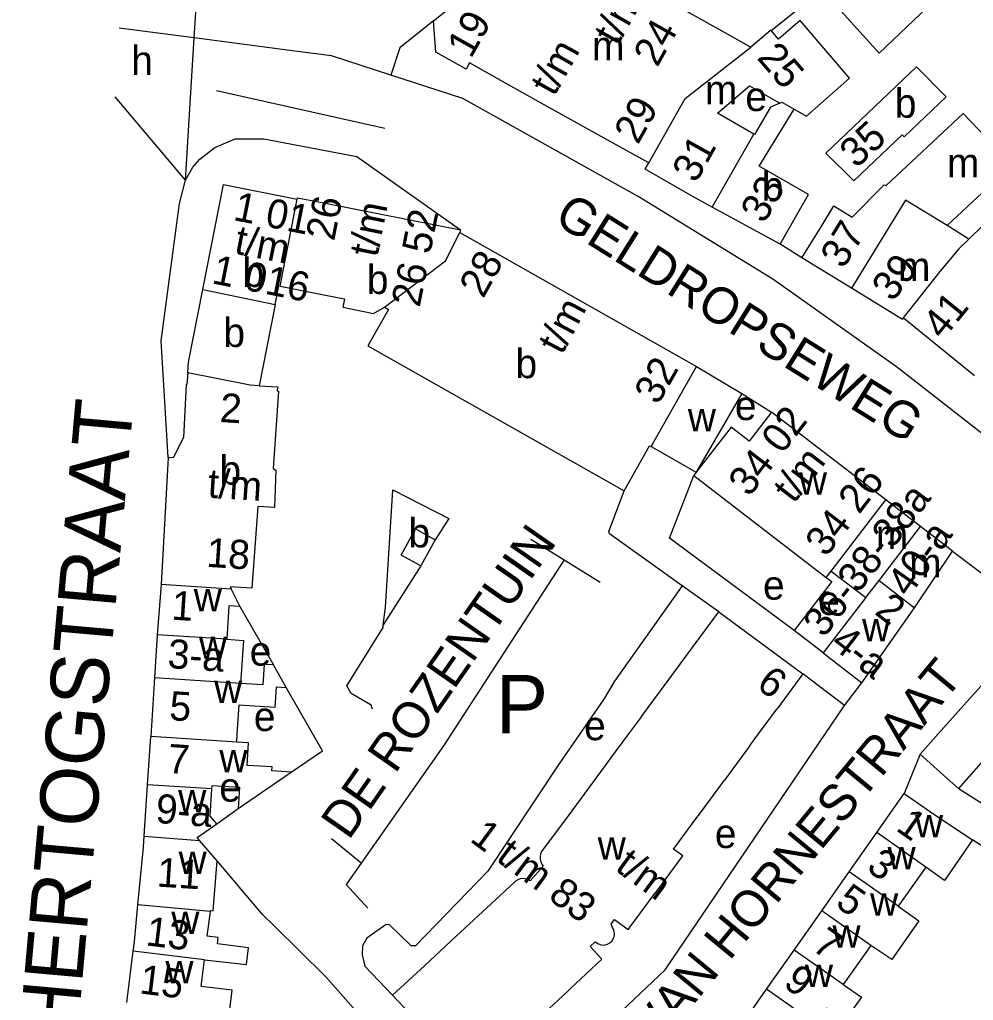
# Model space of a CAD drawing. Extents: x 161141 to 163125, y 381621 to 383200.
# Drawn here: x 161858 to 161989.1, y 382713.4 to 382848.2 of the extents above; entities that cross this region are included whole.
import ezdxf

# ---------------------------------------------------------------- set-up
doc = ezdxf.new("R2010")
doc.units = 0
for name, color, linetype in [('BLT_Basislijn', 7, 'Continuous'), ('BLT_Bebouwing', 7, 'Continuous'), ('BLT_Centroide', 7, 'Continuous'), ('BLT_Huisnummer', 7, 'Continuous'), ('BLT_Huisnummer_ tussenligend', 7, 'Continuous'), ('BLT_Huisnummer_reeks', 7, 'Continuous'), ('BLT_Onderverdeling_panden', 7, 'Continuous'), ('BLT_Straatnaam', 7, 'Continuous'), ('BLT_Straatnaam_hoofdweg', 7, 'Continuous'), ('BLT_Tekst_parkeren', 7, 'Continuous'), ('BLT_Vlakafsluiter', 7, 'Continuous')]:
    doc.layers.add(name, color=color, linetype=linetype)

msp = doc.modelspace()

# ---------------------------------------------------------------- linework, layer by layer
at = {"layer": 'BLT_Basislijn'}
for p, q in [((161961.29, 382846.71), (161968.27, 382852.33)), ((161895.8, 382843.88), (161881.98, 382845.71)), ((161885.05, 382838.45), (161908.16, 382833.27)), ((161965.52, 382815.44), (161962.51, 382817.34)), ((161957.24, 382796.8), (161961.34, 382794.24)), ((161928.24, 382776.76), (161932.83, 382773.93)), ((161913.14, 382773.1), (161907.95, 382764.98)), ((161932.83, 382773.93), (161916.24, 382748.35)), ((161932.83, 382773.93), (161937.79, 382770.88)), ((161954.08, 382766.77), (161949.04, 382770.37)), ((161888.23, 382767.53), (161892.87, 382759.47)), ((161968.43, 382761.13), (161964.43, 382764.21)), ((161971.38, 382753.92), (161965.62, 382758.24)), ((161971.38, 382753.92), (161973.75, 382757.02)), ((161916.24, 382748.35), (161904.92, 382732.23)), ((161981.75, 382747.2), (161979.57, 382741.82)), ((161885.1, 382737.63), (161888.01, 382739.72)), ((161904.92, 382732.23), (161900.83, 382735.55)), ((161996.85, 382730.23), (161988.94, 382735.42)), ((161904.92, 382732.23), (161902.84, 382729.28)), ((161902.84, 382729.28), (161905.85, 382726.02))]:
    msp.add_line(p, q, dxfattribs=at)
for points in [[(162000.63, 382866.97), (161976.12, 382843.61), (161968.27, 382852.33)], [(161914.87, 382848.05), (161910.22, 382844.31), (161909.01, 382840.57)], [(162009.83, 382774.47), (162008.37, 382775.78), (161991.84, 382790.04), (161978.52, 382800.47), (161961.51, 382812.5), (161943, 382823.9), (161918.9, 382837.38), (161909.01, 382840.57)], [(161880.79, 382826.11), (161881.79, 382827.9), (161882.74, 382829.01), (161884.8, 382830.62), (161887.61, 382831.82), (161891.56, 382831.81), (161904.33, 382829.38), (161918.58, 382819.28)], [(161878.4, 382787.98), (161877.45, 382804.06), (161879.93, 382822.9), (161880.79, 382826.11)], [(161964.43, 382764.21), (161947.31, 382776.9), (161950.65, 382785.52)], [(161907.95, 382764.98), (161908.25, 382767.39), (161909.27, 382783.54), (161916.97, 382779.59), (161915.1, 382776.69)], [(161949.04, 382770.37), (161939.06, 382777.49), (161938.96, 382777.81), (161941.06, 382783.4)], [(161949.04, 382770.37), (161939.76, 382757.24), (161938.26, 382754.75), (161932.01, 382745.7), (161922.34, 382731.11), (161912.4, 382720.87), (161911.82, 382720.87), (161908.83, 382723.74), (161908.35, 382723.79), (161905.71, 382721.89), (161905.09, 382720.85), (161905.06, 382719.61), (161905.41, 382718.04), (161909.25, 382714.07)], [(161968.86, 382771.51), (161969.61, 382770.94), (161964.43, 382764.21)], [(161906.5, 382753.39), (161906.28, 382753.96), (161903.53, 382755.56), (161902.94, 382756.61), (161907.93, 382764.64), (161907.95, 382764.98)], [(161895.29, 382744.75), (161899.61, 382747.67), (161894.62, 382756.38)], [(161921.05, 382693.28), (161946.73, 382717.54), (161971.38, 382753.92)], [(161892.98, 382723.59), (161891.37, 382725.18), (161885.15, 382732.53)], [(161892.98, 382723.59), (161900, 382716.62), (161907.64, 382708.03)]]:
    msp.add_lwpolyline(points, dxfattribs=at)
at = {"layer": 'BLT_Bebouwing'}
for p, q in [((161914.87, 382848.05), (161921.65, 382853.48)), ((161915.17, 382843.73), (161914.87, 382848.05)), ((161955.63, 382846.03), (161958.47, 382844.43)), ((161924.76, 382839.48), (161919.83, 382842.24)), ((161929.69, 382836.73), (161924.76, 382839.48)), ((161934.62, 382833.98), (161929.69, 382836.73)), ((161939.55, 382831.22), (161934.62, 382833.98)), ((161944.45, 382828.5), (161939.55, 382831.22)), ((161885.99, 382825.52), (161886.01, 382825.52)), ((161886.01, 382825.52), (161896.14, 382823.52)), ((161962.51, 382817.34), (161953.17, 382822.43)), ((161918.58, 382819.28), (161918.51, 382818.93)), ((161918.51, 382818.93), (161951.04, 382800.5)), ((161988.46, 382818.04), (161985.48, 382819.89)), ((161972.33, 382811.27), (161965.52, 382815.44)), ((161893.11, 382809.05), (161890.89, 382797.86)), ((161989.22, 382799.25), (161979.45, 382807.18)), ((161951.04, 382800.5), (161957.24, 382796.8)), ((161957.24, 382796.8), (161950.99, 382785.97)), ((161977.05, 382782.16), (161961.34, 382794.24)), ((161944.77, 382789.52), (161950.99, 382785.97)), ((161878.4, 382787.98), (161877.41, 382770.53)), ((161950.65, 382785.52), (161968.86, 382771.51)), ((161981.8, 382778.51), (161977.05, 382782.16)), ((161986.22, 382775.11), (161981.8, 382778.51)), ((161915.1, 382776.69), (161913.14, 382773.1)), ((161981, 382767.35), (161986.22, 382775.11)), ((161968.86, 382771.51), (161969.53, 382772.38)), ((161969.53, 382772.38), (161974.28, 382768.73)), ((161877.41, 382770.53), (161876.9, 382763.62)), ((161887.05, 382769.91), (161888.23, 382767.53)), ((161974.28, 382768.73), (161968.43, 382761.13)), ((161950.55, 382761.99), (161954.08, 382766.77)), ((161954.08, 382766.77), (161965.62, 382758.24)), ((161973.75, 382757.02), (161981, 382767.35)), ((161876.9, 382763.62), (161876.51, 382757.72)), ((161946.98, 382757.16), (161950.55, 382761.99)), ((161876.51, 382757.72), (161876, 382749.63)), ((161943.45, 382752.39), (161946.98, 382757.16)), ((161875.57, 382743), (161876, 382749.63)), ((161939.85, 382747.52), (161936.31, 382742.73)), ((161875.11, 382735.95), (161875.57, 382743)), ((161936.31, 382742.73), (161932.72, 382737.87)), ((161975.8, 382736.44), (161979.57, 382741.82)), ((161932.72, 382737.87), (161929.95, 382734.13)), ((161882.7, 382735.36), (161882.38, 382735.74)), ((161885.15, 382732.53), (161882.7, 382735.36)), ((161972.01, 382731.05), (161975.8, 382736.44)), ((161929.96, 382731.82), (161928.15, 382729.78)), ((161982.55, 382731.69), (161978.76, 382726.3)), ((161968.23, 382725.66), (161972.01, 382731.05)), ((161926.01, 382729.6), (161922.86, 382726.68)), ((161922.86, 382726.68), (161917.99, 382722.17)), ((161964.44, 382720.27), (161968.23, 382725.66)), ((161917.99, 382722.17), (161913.62, 382718.11)), ((161974.97, 382720.91), (161971.18, 382715.53)), ((161872.72, 382713.05), (161873.59, 382720.12)), ((161960.66, 382714.88), (161964.44, 382720.27)), ((161913.62, 382718.11), (161909.25, 382714.07)), ((161909.25, 382714.07), (161911.55, 382711.58)), ((161956.87, 382709.48), (161960.66, 382714.88))]:
    msp.add_line(p, q, dxfattribs=at)
for points in [[(161938.14, 382855.85), (161955.63, 382846.03)], [(161964.46, 382835.88), (161966.13, 382834.92), (161972.05, 382840.15), (161965.28, 382848.08), (161962.31, 382845.52), (161961.29, 382846.71)], [(161961.29, 382846.71), (161961.24, 382846.77), (161958.47, 382844.43)], [(161919.83, 382842.24), (161919.34, 382841.39), (161915.17, 382843.73)], [(161958.92, 382832.47), (161953.92, 382835.36), (161958.29, 382839.12), (161962.49, 382836.72)], [(161988.46, 382818.04), (162000.01, 382829.28), (162008.96, 382838), (162018.9, 382827.79)], [(161962.49, 382836.72), (161961.21, 382836.16), (161959, 382832.42), (161958.92, 382832.47)], [(161962.51, 382817.34), (161965.01, 382821.68), (161966.43, 382824.14), (161959.65, 382828.06), (161964.46, 382835.88)], [(161965.52, 382815.44), (161968.14, 382819.7), (161969.92, 382822.6), (161972.43, 382821.05), (161976.82, 382825.48), (161977.11, 382825.39), (161987.67, 382835.28), (161994.1, 382828.62)], [(161953.17, 382822.43), (161950.43, 382823.94), (161943.96, 382827.66), (161944.45, 382828.5)], [(161994.1, 382828.62), (161994.43, 382828.26), (161985.48, 382819.89)], [(161883.15, 382811.11), (161885.39, 382822.51), (161885.99, 382825.52)], [(161896.14, 382823.52), (161896.18, 382823.72), (161900, 382822.97), (161918.58, 382819.28)], [(161881.08, 382799.63), (161881.17, 382801.09), (161883.15, 382811.11)], [(161893.11, 382809.05), (161893.62, 382811.6), (161893.78, 382811.57)], [(161893.78, 382811.57), (161900, 382810.34), (161902.63, 382809.82), (161902.4, 382808.65), (161906.64, 382807.81), (161908.13, 382808.69)], [(161979.45, 382807.18), (161979.33, 382806.98), (161972.33, 382811.27)], [(161908.13, 382808.69), (161908.7, 382808.36), (161905.86, 382803.35), (161941.06, 382783.4)], [(161881.08, 382799.63), (161880.98, 382798.03), (161880.87, 382798.04), (161880.5, 382790.74), (161879.08, 382787.96), (161878.4, 382787.98)], [(161890.89, 382797.86), (161893.43, 382797.71), (161893.4, 382797.15), (161893.55, 382797.14), (161892.85, 382786.5), (161893.21, 382786.26), (161893.01, 382781.11), (161890.7, 382781.26), (161889.91, 382770.03)], [(161961.34, 382794.24), (161958.26, 382790.25), (161955.77, 382792.17), (161950.99, 382785.97)], [(161941.06, 382783.4), (161944.58, 382789.62), (161944.77, 382789.52)], [(161950.99, 382785.97), (161950.65, 382785.52)], [(161913.14, 382773.1), (161910.42, 382774.59), (161912.39, 382778.17), (161915.1, 382776.69)], [(161889.91, 382770.03), (161886.9, 382770.23), (161887.05, 382769.91)], [(161888.23, 382767.53), (161886.75, 382767.62), (161886.45, 382763)], [(161886.45, 382763), (161888.73, 382762.85)], [(161888.73, 382762.85), (161888.34, 382756.94)], [(161968.43, 382761.13), (161969.68, 382760.17), (161973.75, 382757.02)], [(161981.75, 382747.2), (161984.26, 382750), (161994.45, 382761.42)], [(161892.87, 382759.47), (161891.59, 382759.55), (161891.41, 382756.74), (161888.34, 382756.94)], [(161894.62, 382756.38), (161892.87, 382759.47)], [(161965.62, 382758.24), (161962.09, 382753.46)], [(161887.82, 382748.86), (161887.89, 382750), (161888.16, 382754.01), (161893.1, 382753.68), (161893.28, 382756.46), (161894.62, 382756.38)], [(161958.54, 382748.61), (161959.56, 382750), (161961.79, 382753.01), (161962.09, 382753.46)], [(161943.45, 382752.39), (161941.68, 382750), (161939.85, 382747.52)], [(161895.29, 382744.75), (161892.66, 382744.91), (161892.7, 382745.46), (161889.25, 382745.67), (161889.43, 382748.75), (161887.82, 382748.86)], [(161955.04, 382743.82), (161958.23, 382748.14), (161958.54, 382748.61)], [(161987.02, 382742.5), (161985.48, 382743.87), (161981.75, 382747.2)], [(161888.01, 382739.72), (161895.29, 382744.75)], [(161951.43, 382738.95), (161954.66, 382743.31), (161955.04, 382743.82)], [(161885.1, 382737.63), (161884.17, 382738.68), (161884.41, 382742.43)], [(161884.41, 382742.43), (161884.43, 382742.89)], [(161884.43, 382742.89), (161888.19, 382742.66), (161888.01, 382739.72)], [(161997.28, 382742.34), (161993.65, 382738.27), (161987.14, 382742.39), (161987.02, 382742.5)], [(161979.57, 382741.82), (161983.66, 382738.95), (161988.94, 382735.42)], [(161947.88, 382734.17), (161951.08, 382738.49), (161951.43, 382738.95)], [(161882.38, 382735.74), (161885.1, 382737.63)], [(161874.23, 382726.5), (161875.01, 382734.4), (161875.11, 382735.95)], [(161988.94, 382735.42), (161985.11, 382729.84), (161982.55, 382731.69)], [(161929.95, 382734.13), (161929.73, 382733.83), (161929.58, 382733.49), (161929.51, 382733.14), (161929.51, 382732.77), (161929.6, 382732.41), (161929.76, 382732.08), (161929.96, 382731.82)], [(161949.15, 382733.23), (161947.88, 382734.17)], [(161945.56, 382728.37), (161949.15, 382733.23)], [(161884.23, 382725.71), (161884.6, 382725.66), (161885.15, 382732.53)], [(161928.15, 382729.78), (161927.84, 382729.96), (161927.49, 382730.07), (161927.14, 382730.1), (161926.78, 382730.05), (161926.45, 382729.93), (161926.15, 382729.73), (161926.01, 382729.6)], [(161941.63, 382723.09), (161945.17, 382727.87), (161945.56, 382728.37)], [(161873.59, 382720.12), (161873.76, 382721.46), (161874.23, 382726.5)], [(161978.76, 382726.3), (161981.6, 382724.3), (161977.85, 382718.97), (161974.97, 382720.91)], [(161883.37, 382718.92), (161887.53, 382718.47), (161889.15, 382718.29), (161889.45, 382720.58), (161885.18, 382721.14), (161885.29, 382721.98), (161883.76, 382722.19), (161884.21, 382725.56)], [(161884.21, 382725.56), (161884.23, 382725.71)], [(161937.44, 382721.16), (161937.77, 382721.03), (161938.12, 382720.97), (161938.47, 382720.99), (161938.8, 382721.1), (161939.11, 382721.27), (161939.37, 382721.51), (161939.56, 382721.8), (161939.69, 382722.13), (161939.74, 382722.48), (161939.71, 382722.83), (161939.6, 382723.16), (161939.49, 382723.37)], [(161939.49, 382723.37), (161939.28, 382723.82), (161939.76, 382724.47)], [(161939.76, 382724.47), (161941.63, 382723.09)], [(161936.39, 382720.78), (161937.07, 382721.41), (161937.44, 382721.16)], [(161938.01, 382719.03), (161936.39, 382720.78)], [(161883.19, 382717.45), (161883.37, 382718.92)], [(161933.68, 382715.01), (161938.01, 382719.03)], [(161886.79, 382711.32), (161887.21, 382714.74), (161882.92, 382715.26), (161883.19, 382717.45)], [(161971.18, 382715.53), (161973.69, 382713.82), (161971.37, 382710.53), (161968.89, 382712.27), (161967.39, 382710.14)], [(161928.84, 382710.46), (161933.28, 382714.57), (161933.68, 382715.01)]]:
    msp.add_lwpolyline(points, dxfattribs=at)
msp.add_lwpolyline([(161981.28, 382841.69), (161968.8, 382829.84), (161972.65, 382826.03), (161979.28, 382832.35), (161979.55, 382832.07), (161985.35, 382837.6)], close=True, dxfattribs=at)
at = {"layer": 'BLT_Onderverdeling_panden'}
for p, q in [((161949.46, 382837.35), (161958.47, 382844.43)), ((161944.45, 382828.5), (161949.46, 382837.35)), ((161953.17, 382822.43), (161958.92, 382832.47)), ((161893.78, 382811.57), (161896.14, 382823.52)), ((161883.15, 382811.11), (161893.11, 382809.05)), ((161944.77, 382789.52), (161951.04, 382800.5)), ((161969.53, 382772.38), (161977.05, 382782.16)), ((161976.11, 382771.11), (161981.8, 382778.51)), ((161887.05, 382769.91), (161877.41, 382770.53)), ((161974.28, 382768.73), (161976.11, 382771.11)), ((161976.11, 382771.11), (161981, 382767.35)), ((161888.34, 382756.94), (161876.51, 382757.72)), ((161887.82, 382748.86), (161876, 382749.63)), ((161991.49, 382747.51), (161987.02, 382742.5)), ((161884.41, 382742.43), (161875.57, 382743)), ((161875.11, 382735.95), (161882.7, 382735.36)), ((161982.55, 382731.69), (161975.8, 382736.44)), ((161978.76, 382726.3), (161972.01, 382731.05)), ((161884.21, 382725.56), (161874.23, 382726.5)), ((161974.97, 382720.91), (161968.23, 382725.66)), ((161883.37, 382718.92), (161873.59, 382720.12)), ((161971.18, 382715.53), (161964.44, 382720.27)), ((161967.39, 382710.14), (161960.66, 382714.88))]:
    msp.add_line(p, q, dxfattribs=at)
for points in [[(161962.49, 382836.72), (161962.77, 382836.85), (161964.46, 382835.88)], [(161985.48, 382819.89), (161979.75, 382823.38), (161972.33, 382811.27)], [(161908.13, 382808.69), (161916.53, 382815.04), (161918.51, 382818.93)], [(161988.46, 382818.04), (161987.09, 382816.7), (161984.48, 382813.59), (161979.45, 382807.18)], [(161890.89, 382797.86), (161889.67, 382797.93), (161881.08, 382799.63)], [(161886.45, 382763), (161876.9, 382763.62)]]:
    msp.add_lwpolyline(points, dxfattribs=at)
at = {"layer": 'BLT_Vlakafsluiter'}
for p, q in [((161881.98, 382845.71), (161882.4, 382852.74)), ((161881.98, 382845.71), (161871.64, 382847.05)), ((161880.79, 382826.11), (161881.98, 382845.71)), ((161880.79, 382826.11), (161871.13, 382837.57)), ((161986.22, 382775.11), (161998.45, 382765.9))]:
    msp.add_line(p, q, dxfattribs=at)
msp.add_lwpolyline([(161909.01, 382840.57), (161900.83, 382843.22), (161895.8, 382843.88)], dxfattribs=at)

# ---------------------------------------------------------------- texts
at = {"layer": 'BLT_Centroide'}
for s, p in [('h', (161873.31, 382840.6)), ('m', (161936.66, 382842.62)), ('m', (161952.18, 382836.56)), ('e', (161957.73, 382835.63)), ('b', (161978.28, 382834.72)), ('m', (161985.45, 382826.53)), ('b', (161960, 382823.31)), ('b', (161888.61, 382811.45)), ('m', (161978.72, 382812.25)), ('b', (161905.7, 382810.49)), ('b', (161885.99, 382803.19)), ('b', (161926.14, 382798.91)), ('e', (161956.3, 382793.14)), ('w', (161949.83, 382791.59)), ('b', (161885.45, 382784.27)), ('w', (161965.1, 382782.88)), ('b', (161911.43, 382775.64)), ('m', (161975.67, 382775.44)), ('m', (161980.25, 382771.53)), ('e', (161960.16, 382768.45)), ('w', (161881.91, 382766.84)), ('e', (161967.74, 382766.35)), ('w', (161973.78, 382762.72)), ('w', (161882.62, 382760.28)), ('e', (161889.6, 382759.38)), ('w', (161884.71, 382754.25)), ('e', (161890.17, 382750.39)), ('e', (161935.57, 382749.13)), ('w', (161885.43, 382744.69)), ('e', (161885.42, 382740.68)), ('w', (161879.77, 382739.19)), ('w', (161981.06, 382735.77)), ('e', (161953.54, 382734.3)), ('w', (161937.44, 382732.7)), ('w', (161977.28, 382731.38)), ('w', (161879.83, 382730.75)), ('w', (161974.88, 382725)), ('w', (161878.83, 382722.47)), ('w', (161969.71, 382720.59)), ('w', (161878.02, 382715.72)), ('w', (161965.92, 382715.19))]:
    msp.add_text(s, height=4, dxfattribs=at).set_placement(p)
at = {"layer": 'BLT_Huisnummer'}
for s, rotation, p in [('35', 42.4989, (161972.99, 382827.65)), ('33', 60.0462, (161960.32, 382820.02)), ('37', 58.4989, (161971.22, 382813.8)), ('39', 51.8621, (161977.96, 382809.27)), ('41', 50.9095, (161984.88, 382804.05)), ('1', 356.2158, (161878.76, 382765.72)), ('5', 356.218, (161878.47, 382751.91)), ('1', 324.8704, (161978.28, 382736.82)), ('5', 324.8679, (161969.95, 382726.4)), ('13', 352.9976, (161875.21, 382720.94)), ('9', 324.8671, (161962.78, 382715.34))]:
    msp.add_text(s, height=4, rotation=rotation, dxfattribs=at).set_placement(p)
at = {"layer": 'BLT_Huisnummer_ tussenligend'}
for s, rotation, p in [('7', 356.218, (161878.24, 382744.64)), ('3', 324.8704, (161974.23, 382731.31)), ('11', 356.3888, (161876.77, 382729.01)), ('7', 324.8679, (161966.71, 382720.41)), ('15', 352.9976, (161874.33, 382714.33))]:
    msp.add_text(s, height=4, rotation=rotation, dxfattribs=at).set_placement(p)
at = {"layer": 'BLT_Huisnummer_reeks'}
for s, rotation, p in [('t/m', 60.6939, (161940.16, 382844.48)), ('19', 60.7317, (161920.01, 382842.73)), ('24', 60.6972, (161945.63, 382841.55)), ('t/m', 60.6939, (161931.45, 382837.52)), ('25', 310.7051, (161959.21, 382842.91)), ('29', 60.7317, (161942.97, 382830.91)), ('31', 60.8038, (161950.95, 382825.6)), ('1 01', 348.8024, (161887.21, 382820.66)), ('26', 78.798, (161901.2, 382817.65)), ('t/m', 78.798, (161907.14, 382815.42)), ('26 52', 78.798, (161912.96, 382808.54)), ('t/m', 348.8024, (161887.35, 382816.07)), ('28', 60.9845, (161921.7, 382809.75)), ('1 016', 348.8024, (161884.26, 382811.97)), ('t/m', 62.0702, (161932.53, 382801.99)), ('32', 60.2402, (161945.72, 382795.09)), ('2', 356.2278, (161885.41, 382792.89)), ('34 02', 52.4331, (161958.27, 382782.45)), ('t/m', 52.4259, (161964.41, 382781.54)), ('34 26', 52.4351, (161968.83, 382774.18)), ('t/m', 356.2186, (161883.76, 382782.5)), ('36-38-38a', 52.4323, (161968.54, 382763.08)), ('40-a', 55.038, (161980.22, 382768.64)), ('18', 356.2186, (161883.57, 382772.98)), ('2', 322.4354, (161975.35, 382766.57)), ('4-a', 322.4426, (161969.27, 382762.09)), ('3-a', 356.2158, (161878.24, 382759.06)), ('6', 323.5168, (161959.08, 382756.42)), ('9-a', 355.5765, (161876.58, 382737.78)), ('1 t/m 83', 323.5174, (161919.72, 382735.33)), ('t/m', 323.5168, (161939.67, 382731.35))]:
    msp.add_text(s, height=4, rotation=rotation, dxfattribs=at).set_placement(p)
at = {"layer": 'BLT_Straatnaam'}
for s, rotation, p in [('GELDROPSEWEG', 327.9765, (161931.24, 382820.36)), ('DE ROZENTUIN', 55.0763, (161903.21, 382735.26)), ('WILLEM VAN HORNESTRAAT', 50.3955, (161928.08, 382685.49))]:
    msp.add_text(s, height=5, rotation=rotation, dxfattribs=at).set_placement(p)
at = {"layer": 'BLT_Straatnaam_hoofdweg'}
msp.add_text('HERTOGSTRAAT', height=7.9999, rotation=84.9196, dxfattribs=at).set_placement((161865.87, 382707.94))
at = {"layer": 'BLT_Tekst_parkeren'}
msp.add_text('P', height=8, dxfattribs=at).set_placement((161923.47, 382750.09))

doc.saveas('drawing.dxf')
